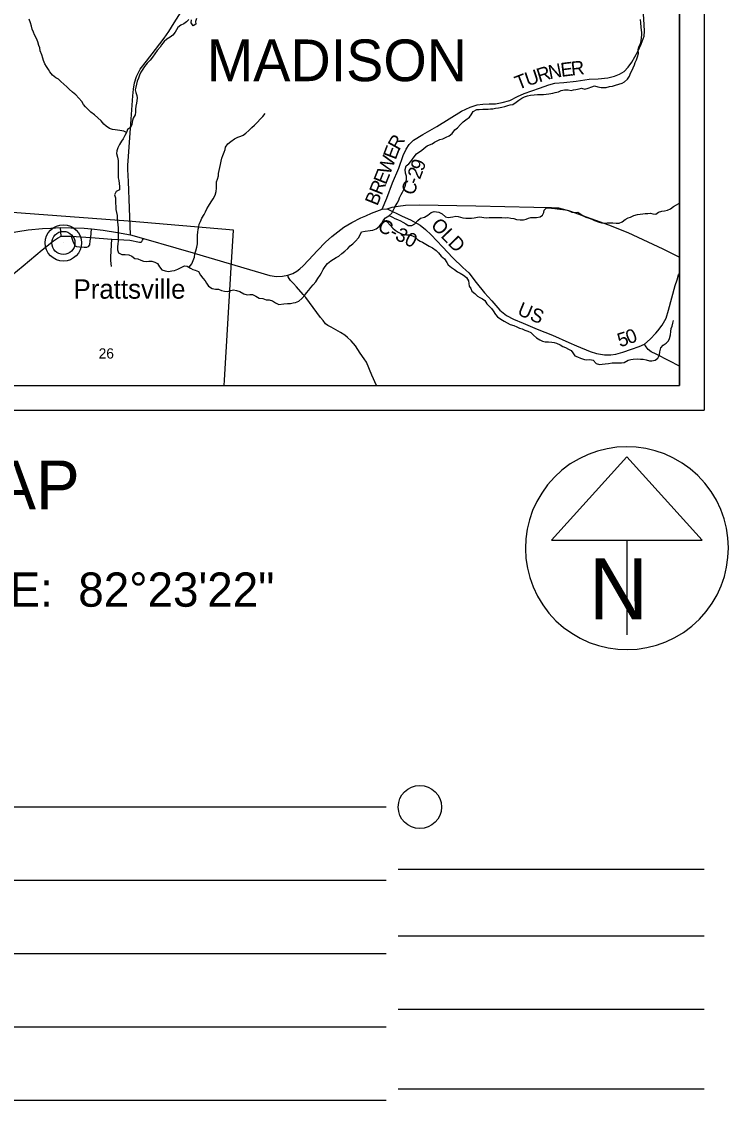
# Model space of a CAD drawing. Extents: x 0 to 34, y 0 to 22.
# Drawn here: x 6.21 to 9.099, y 11.177 to 15.589 of the extents above; entities that cross this region are included whole.
import ezdxf

# ---------------------------------------------------------------- set-up
doc = ezdxf.new("R2010")
doc.units = 0
for name, color, linetype in [('Default', 7, 'Continuous'), ('GM_X_County_Road', 7, 'Continuous'), ('GM_X_County_Road_Text', 7, 'Continuous'), ('GM_X_Minor_River', 7, 'Continuous'), ('GM_X_Section_Text', 7, 'Continuous'), ('GM_X_State_Route', 7, 'Continuous'), ('GM_X_Township_Road', 7, 'Continuous'), ('GM_X_Township_Text', 7, 'Continuous'), ('GM_X_Unincorporated', 7, 'Continuous'), ('GM_X_Unincorporated_Location', 7, 'Continuous'), ('GM_X_Unincorporated_Text', 7, 'Continuous'), ('GM_X_US_Route', 7, 'Continuous'), ('SC_Scratch1', 7, 'Continuous'), ('SH_Data', 7, 'Continuous'), ('SH_Text', 7, 'Continuous')]:
    doc.layers.add(name, color=color, linetype=linetype)

msp = doc.modelspace()

# ---------------------------------------------------------------- linework, layer by layer
at = {"layer": 'Default'}
msp.add_lwpolyline([(6.0561, 14.1), (7.0384, 14.1), (7.0398, 14.1229), (7.0661, 14.5598), (7.0761, 14.7365), (6.6458, 14.7734), (6.1161, 14.8127)], close=True, dxfattribs=at)
at = {"layer": 'GM_X_County_Road'}
for points in [[(7.6842, 14.8215), (7.7027, 14.8671), (7.7267, 14.9301), (7.7517, 14.9896), (7.7701, 15.0412), (7.7821, 15.0675), (7.7941, 15.0865), (7.8128, 15.1036), (7.8505, 15.1277), (7.9072, 15.1601), (8.0084, 15.2229), (8.0433, 15.2391), (8.0724, 15.2486), (8.0952, 15.2514), (8.1215, 15.2524), (8.1477, 15.253), (8.174, 15.2574), (8.206, 15.2663), (8.2379, 15.2831), (8.2642, 15.2954), (8.3269, 15.3173), (8.3652, 15.3299), (8.3893, 15.3372), (8.4272, 15.3404), (8.4773, 15.3454), (8.5301, 15.3534), (8.5672, 15.3549), (8.6061, 15.3584), (8.6336, 15.3654), (8.6545, 15.3733), (8.6729, 15.385), (8.6897, 15.4027), (8.7052, 15.4227), (8.7289, 15.4664), (8.7422, 15.4964), (8.7549, 15.529), (8.7568, 15.5503), (8.7555, 15.5753), (8.7526, 15.6202)], [(7.7042, 14.8235), (7.7656, 14.7937), (7.8006, 14.7775), (7.8391, 14.7557), (7.8619, 14.7386), (7.8844, 14.7165), (7.9302, 14.6678), (7.9733, 14.6221), (8.0133, 14.583), (8.0379, 14.5614), (8.068, 14.5218), (8.1018, 14.4791), (8.1322, 14.4467), (8.1645, 14.4085), (8.1917, 14.3863), (8.2212, 14.3717), (8.2604, 14.3559), (8.3171, 14.3312), (8.3807, 14.3058), (8.4472, 14.2768), (8.4788, 14.2632), (8.5339, 14.2401), (8.5599, 14.2309), (8.5928, 14.2264), (8.6184, 14.2264), (8.639, 14.229), (8.6678, 14.2363), (8.7033, 14.2486), (8.7343, 14.2603), (8.7564, 14.27)], [(6.147, 14.5332), (6.2168, 14.5903), (6.2945, 14.6549), (6.3413, 14.6925), (6.3566, 14.7035), (6.3721, 14.7117), (6.4137, 14.7116), (6.4931, 14.7064), (6.5788, 14.6994), (6.6531, 14.6952), (6.6926, 14.6869), (6.6988, 14.6871), (6.7013, 14.6898), (6.7047, 14.6951), (6.7093, 14.7021)], [(8.7564, 14.27), (8.7792, 14.2907), (8.8023, 14.3144), (8.8109, 14.3239), (8.8289, 14.3471), (8.8445, 14.3765), (8.8543, 14.4081), (8.8685, 14.4597), (8.8824, 14.5098), (8.8894, 14.5329), (8.8951, 14.5537), (8.9, 14.5591)], [(8.9, 14.1792), (8.8566, 14.2017), (8.8037, 14.2284), (8.7835, 14.238), (8.7717, 14.2484), (8.7633, 14.2588), (8.7564, 14.27)]]:
    msp.add_lwpolyline(points, dxfattribs=at)
at = {"layer": 'GM_X_Minor_River'}
for points in [[(6.286, 15.4699), (6.2845, 15.4822), (6.281, 15.4917), (6.2765, 15.5057), (6.2719, 15.5194), (6.2635, 15.5345), (6.2593, 15.5451), (6.2543, 15.558), (6.2509, 15.5705), (6.247, 15.5838), (6.2417, 15.5985)], [(6.8939, 15.5979), (6.8849, 15.5884), (6.8739, 15.58), (6.8615, 15.5739), (6.8497, 15.5648), (6.843, 15.5549), (6.8388, 15.5454), (6.8283, 15.5332), (6.8177, 15.5256), (6.8045, 15.5165), (6.7932, 15.507), (6.7818, 15.4945), (6.7766, 15.485), (6.7641, 15.4702)], [(6.925, 15.6021), (6.9212, 15.5888), (6.922, 15.5778), (6.9122, 15.571), (6.9034, 15.5835), (6.9053, 15.5964)], [(8.7308, 15.4736), (8.7338, 15.4855), (8.7395, 15.498), (8.7421, 15.5105), (8.744, 15.5223), (8.7455, 15.5348), (8.7455, 15.5447), (8.7447, 15.5545), (8.7432, 15.5655), (8.7409, 15.5845), (8.7405, 15.5978)], [(6.6394, 15.1354), (6.6278, 15.1408), (6.6123, 15.1439), (6.6025, 15.145), (6.5926, 15.1458), (6.5824, 15.1474), (6.5692, 15.1523), (6.556, 15.1607), (6.5461, 15.1701), (6.5352, 15.1827), (6.5216, 15.1956), (6.5088, 15.2073), (6.4937, 15.2191), (6.4827, 15.2294), (6.4718, 15.24), (6.4631, 15.2502), (6.4567, 15.2627), (6.4442, 15.2764), (6.4321, 15.2893), (6.4185, 15.2999), (6.4049, 15.3128), (6.3951, 15.3223), (6.383, 15.3326), (6.371, 15.3444), (6.3611, 15.3531), (6.3498, 15.3588), (6.3373, 15.3702), (6.3264, 15.3831), (6.3211, 15.3933), (6.3124, 15.4058), (6.306, 15.4161), (6.2996, 15.4293), (6.297, 15.4388), (6.2928, 15.4529), (6.286, 15.4699)], [(6.7641, 15.4702), (6.755, 15.4567), (6.7455, 15.4435), (6.7353, 15.4306), (6.7243, 15.4192), (6.7122, 15.4052), (6.7065, 15.395), (6.6974, 15.3818), (6.6925, 15.3696), (6.6883, 15.3579), (6.6833, 15.3458), (6.6807, 15.3337), (6.6776, 15.3212), (6.6746, 15.3094), (6.6776, 15.2996), (6.6821, 15.287), (6.6832, 15.2772), (6.6821, 15.2643), (6.6798, 15.2548), (6.6771, 15.2431), (6.6756, 15.2302), (6.6763, 15.2181), (6.6748, 15.2082), (6.6661, 15.1935), (6.6619, 15.1791), (6.6615, 15.1666), (6.6554, 15.156), (6.6437, 15.1473), (6.6391, 15.1348), (6.6323, 15.1226), (6.6259, 15.1101), (6.619, 15.1003), (6.6111, 15.0863), (6.6039, 15.073), (6.5997, 15.0605), (6.5985, 15.0488), (6.6023, 15.0351), (6.6049, 15.0215), (6.6056, 15.0086), (6.6056, 14.9991), (6.6048, 14.987), (6.6048, 14.9643), (6.6055, 14.9506), (6.6082, 14.9385), (6.6093, 14.9264), (6.6108, 14.9142), (6.6108, 14.9014), (6.5968, 14.8946), (6.5907, 14.8809), (6.5944, 14.8688), (6.594, 14.8552), (6.5948, 14.8445), (6.5959, 14.8339), (6.5963, 14.8203), (6.5989, 14.8078), (6.6004, 14.7956), (6.6011, 14.7828), (6.6018, 14.7695), (6.6033, 14.7574), (6.6052, 14.7449), (6.6056, 14.7316), (6.6052, 14.7179), (6.6055, 14.7058), (6.6051, 14.6922), (6.6036, 14.6793), (6.6028, 14.6691), (6.6028, 14.6558), (6.6069, 14.6433), (6.6198, 14.6361), (6.6342, 14.6364), (6.6485, 14.6353), (6.661, 14.6299), (6.6727, 14.6197), (6.6852, 14.6182), (6.698, 14.6128), (6.7082, 14.6087), (6.7207, 14.6075), (6.7305, 14.6094), (6.743, 14.6094), (6.7551, 14.6052), (6.7665, 14.5991), (6.7744, 14.5866), (6.7834, 14.5733), (6.7978, 14.5702), (6.8114, 14.5672), (6.8243, 14.5691), (6.8349, 14.5713), (6.8489, 14.5758), (6.8621, 14.5838), (6.8761, 14.5898), (6.8878, 14.5887), (6.9003, 14.5807), (6.9105, 14.5754), (6.9203, 14.572), (6.9332, 14.5662), (6.9411, 14.5518), (6.9517, 14.5393), (6.9604, 14.5291), (6.966, 14.5196), (6.9743, 14.5067), (6.9887, 14.4976)], [(8.2555, 15.2757), (8.2654, 15.2818), (8.2783, 15.2856), (8.2904, 15.2875), (8.3059, 15.289), (8.3192, 15.2902), (8.3332, 15.2906), (8.3442, 15.291), (8.3548, 15.2921), (8.365, 15.2933), (8.3813, 15.2967), (8.3915, 15.299), (8.4051, 15.3017), (8.4157, 15.3066), (8.4294, 15.31), (8.4441, 15.3093), (8.4566, 15.3074), (8.4665, 15.3105), (8.4763, 15.3109), (8.4888, 15.3139), (8.4987, 15.3166), (8.5131, 15.3128), (8.5263, 15.3166), (8.5411, 15.3227), (8.5517, 15.3258), (8.5653, 15.3224), (8.5786, 15.3197), (8.5892, 15.3194), (8.5994, 15.3198), (8.6127, 15.324), (8.6256, 15.3255), (8.6384, 15.3285), (8.6517, 15.3335), (8.6646, 15.3365), (8.6752, 15.3426), (8.6869, 15.3529), (8.6945, 15.3662), (8.6997, 15.3779), (8.7043, 15.3874), (8.7103, 15.4003), (8.7152, 15.4121), (8.7186, 15.4216), (8.7232, 15.4329), (8.7284, 15.4455), (8.7315, 15.4587), (8.7308, 15.4736)], [(7.2616, 14.4317), (7.2823, 14.4347), (7.2971, 14.4363), (7.31, 14.4366), (7.3198, 14.4382), (7.33, 14.4401), (7.3433, 14.4462), (7.3562, 14.4568), (7.3675, 14.4697), (7.3747, 14.4792), (7.3845, 14.4906), (7.3928, 14.5012), (7.4019, 14.5122), (7.4125, 14.5248), (7.4216, 14.5384), (7.4303, 14.5513), (7.436, 14.5612), (7.4435, 14.5745), (7.4511, 14.5874), (7.4613, 14.5995), (7.4738, 14.6106), (7.4855, 14.6178), (7.4961, 14.6239), (7.5071, 14.6299), (7.5199, 14.6398), (7.5321, 14.6497), (7.5442, 14.6611), (7.5536, 14.6713), (7.5638, 14.6801), (7.5756, 14.6911), (7.5873, 14.704), (7.5941, 14.7165), (7.5998, 14.7294), (7.6149, 14.7325), (7.6354, 14.734), (7.646, 14.7356), (7.66, 14.7409), (7.6725, 14.7512), (7.6827, 14.7648), (7.6895, 14.7766), (7.6982, 14.7868), (7.7114, 14.7944), (7.7232, 14.8058), (7.7311, 14.8187), (7.7379, 14.8328), (7.7458, 14.8457), (7.7519, 14.8582), (7.7557, 14.8681), (7.7617, 14.8813), (7.7674, 14.8916), (7.7738, 14.9056), (7.7798, 14.9193), (7.7828, 14.9341), (7.784, 14.9458), (7.7832, 14.9565), (7.779, 14.9697), (7.7786, 14.9841), (7.782, 14.9986), (7.7926, 15.0069), (7.8009, 15.0164), (7.8085, 15.0259), (7.8149, 15.0365), (7.824, 15.0479), (7.8346, 15.0544), (7.8456, 15.062), (7.8562, 15.0719), (7.8683, 15.0802), (7.8781, 15.0848), (7.8883, 15.089), (7.8982, 15.0958), (7.9084, 15.1019), (7.9201, 15.1065), (7.9315, 15.1099), (7.9459, 15.1163), (7.9584, 15.1224), (7.9697, 15.1315), (7.9811, 15.1456), (7.9924, 15.1551), (8.0045, 15.168), (8.0159, 15.1794), (8.0265, 15.1874), (8.0405, 15.1976), (8.0473, 15.2071), (8.0564, 15.2208), (8.0707, 15.2288), (8.0806, 15.2299), (8.095, 15.2307), (8.1067, 15.2303), (8.1173, 15.2304), (8.1272, 15.2319), (8.137, 15.2327), (8.1476, 15.2342), (8.1598, 15.2361), (8.173, 15.2384), (8.1859, 15.2418), (8.198, 15.2456), (8.2078, 15.2483), (8.2181, 15.2502), (8.2321, 15.2597), (8.2423, 15.2673), (8.2555, 15.2757)], [(6.8951, 14.584), (6.9064, 14.5977), (6.9117, 14.6114), (6.9174, 14.6261), (6.9189, 14.6394), (6.9227, 14.6519), (6.9265, 14.6663), (6.9288, 14.6796), (6.9289, 14.6906), (6.9296, 14.7034), (6.93, 14.7167), (6.9304, 14.7269), (6.932, 14.7402), (6.9342, 14.7497), (6.9369, 14.7599), (6.9415, 14.772), (6.9475, 14.7853), (6.9566, 14.8), (6.9623, 14.811), (6.968, 14.8235), (6.9741, 14.8345), (6.9851, 14.8512), (6.9931, 14.864), (7.001, 14.8788), (7.0056, 14.8943), (7.0075, 14.9072), (7.0075, 14.933), (7.0106, 14.9443), (7.0148, 14.958), (7.0159, 14.9682), (7.0182, 14.9803), (7.0209, 14.9921), (7.0228, 15.0038), (7.0262, 15.0178), (7.0285, 15.03), (7.0331, 15.0413), (7.0388, 15.055), (7.0426, 15.0652), (7.0445, 15.0747), (7.0532, 15.089), (7.0657, 15.0989), (7.0808, 15.1098), (7.0937, 15.1159), (7.1066, 15.1197), (7.1164, 15.1238), (7.1274, 15.1333), (7.1387, 15.1431), (7.1512, 15.1552), (7.1626, 15.1651), (7.1751, 15.1779), (7.185, 15.1897), (7.1963, 15.2002), (7.2066, 15.2135)], [(7.7124, 14.7954), (7.7266, 14.7884), (7.7361, 14.7839), (7.7463, 14.7793), (7.7588, 14.7744), (7.7687, 14.7683), (7.7812, 14.7623), (7.791, 14.7555), (7.805, 14.7547), (7.8183, 14.7623), (7.83, 14.7756), (7.841, 14.7848), (7.8569, 14.7886), (7.8709, 14.7969), (7.8838, 14.8083), (7.897, 14.8129), (7.9065, 14.8106), (7.9163, 14.8099), (7.9292, 14.8027), (7.9433, 14.791), (7.9535, 14.7879), (7.9633, 14.7891), (7.9736, 14.7902), (7.9853, 14.7925), (7.9951, 14.7922), (8.0046, 14.7895), (8.0145, 14.7861), (8.0258, 14.785), (8.0368, 14.785), (8.0489, 14.7854), (8.0603, 14.787), (8.0732, 14.7885), (8.083, 14.79), (8.0993, 14.7881), (8.1107, 14.787), (8.1209, 14.7874), (8.1308, 14.7874), (8.1421, 14.7878), (8.1531, 14.7882), (8.1626, 14.7882), (8.1736, 14.7871), (8.1868, 14.7864), (8.1982, 14.7871), (8.2103, 14.7856), (8.2217, 14.783), (8.2338, 14.78), (8.2482, 14.7777), (8.2615, 14.7778), (8.2721, 14.7808), (8.2819, 14.785), (8.2921, 14.7873), (8.3024, 14.7873), (8.3149, 14.7881), (8.3296, 14.7911), (8.3398, 14.7976), (8.3448, 14.8078), (8.3463, 14.8181), (8.3561, 14.8272), (8.3656, 14.8272), (8.3762, 14.8261), (8.3894, 14.8242), (8.3989, 14.8235), (8.4103, 14.8223), (8.4228, 14.8208), (8.4338, 14.8193), (8.4463, 14.8163), (8.4588, 14.8095), (8.4713, 14.8088), (8.4845, 14.8092), (8.4955, 14.802), (8.5054, 14.7944), (8.5164, 14.7887), (8.53, 14.785), (8.541, 14.7808), (8.5524, 14.7755), (8.5668, 14.7695), (8.5804, 14.7653), (8.5899, 14.7646), (8.6035, 14.7665), (8.6172, 14.7665), (8.6266, 14.7657), (8.6403, 14.7639), (8.6535, 14.7646), (8.6645, 14.77), (8.6774, 14.7802), (8.6891, 14.7867), (8.699, 14.789), (8.7122, 14.7954), (8.7274, 14.8004), (8.7387, 14.8012), (8.7489, 14.8023), (8.7595, 14.8046), (8.7705, 14.8042), (8.7808, 14.8058), (8.791, 14.8028), (8.8031, 14.802), (8.8133, 14.8092), (8.8277, 14.8134), (8.8383, 14.815), (8.8504, 14.8173), (8.8622, 14.823)], [(8.8622, 14.823), (8.8754, 14.8332), (8.8868, 14.8397), (8.8966, 14.845), (8.9, 14.8473)], [(7.6898, 14.777), (7.7043, 14.7705), (7.7164, 14.7561), (7.7274, 14.744), (7.7369, 14.7361), (7.749, 14.7281), (7.7634, 14.7213), (7.7729, 14.7179), (7.7831, 14.7168), (7.7949, 14.7164), (7.8081, 14.7134), (7.8184, 14.707), (7.8282, 14.6979), (7.8392, 14.6903), (7.8487, 14.6862), (7.8631, 14.6786), (7.876, 14.6703), (7.8896, 14.6642), (7.9044, 14.6521), (7.9143, 14.6434), (7.9256, 14.6301), (7.9385, 14.6184), (7.9484, 14.6036), (7.9541, 14.5938), (7.9674, 14.5832), (7.9803, 14.5749), (7.9916, 14.5658), (8.0034, 14.5605), (8.0163, 14.5525), (8.0284, 14.5419), (8.0368, 14.529), (8.0387, 14.5177), (8.0398, 14.5063), (8.0463, 14.4968), (8.0512, 14.4862), (8.0633, 14.4768), (8.0732, 14.4658), (8.0827, 14.4612), (8.0937, 14.4556), (8.1032, 14.4476), (8.1126, 14.4347), (8.121, 14.4249), (8.1305, 14.4154), (8.1373, 14.4056), (8.1468, 14.3915), (8.1559, 14.3813), (8.1688, 14.3715), (8.1824, 14.3635), (8.1957, 14.3571), (8.2078, 14.3503), (8.2226, 14.3454), (8.2351, 14.3405), (8.2457, 14.3356), (8.256, 14.3318), (8.2677, 14.3272), (8.2802, 14.3223), (8.2923, 14.3174), (8.3033, 14.3061), (8.3147, 14.2954), (8.328, 14.2871), (8.3401, 14.2826), (8.3503, 14.2796), (8.3636, 14.2796), (8.3772, 14.2777), (8.3867, 14.2758), (8.3966, 14.2736), (8.4113, 14.2668), (8.4231, 14.2607), (8.4337, 14.2554), (8.4455, 14.249), (8.4572, 14.2437), (8.464, 14.2338), (8.472, 14.2225), (8.4819, 14.2183), (8.4947, 14.2119), (8.5114, 14.2066), (8.5209, 14.2055), (8.5334, 14.2063), (8.5463, 14.2036), (8.5584, 14.1907), (8.572, 14.1862), (8.583, 14.1881), (8.5952, 14.1893), (8.6088, 14.1901), (8.6243, 14.1927), (8.6345, 14.1931), (8.6512, 14.1935), (8.6622, 14.1935), (8.6739, 14.1951), (8.6898, 14.2038), (8.7004, 14.2069), (8.7103, 14.208), (8.7277, 14.2092), (8.7394, 14.2084), (8.7504, 14.2081), (8.7637, 14.2058), (8.777, 14.2013), (8.7864, 14.2013), (8.7993, 14.2043), (8.8114, 14.212), (8.8182, 14.2264)], [(6.9887, 14.4976), (7.0023, 14.4941), (7.0148, 14.4941), (7.0276, 14.4896), (7.0401, 14.4861), (7.0533, 14.4857), (7.0662, 14.4895), (7.0772, 14.4918), (7.0889, 14.4895), (7.1029, 14.4849), (7.1184, 14.475), (7.1323, 14.4708), (7.1433, 14.4727), (7.1543, 14.4727), (7.1675, 14.4658), (7.1819, 14.4579), (7.1962, 14.4571), (7.2098, 14.451), (7.2223, 14.4506), (7.2359, 14.4468), (7.248, 14.4388), (7.2616, 14.4317)], [(8.8182, 14.2264), (8.8193, 14.2385), (8.8231, 14.2548), (8.8329, 14.2658), (8.8443, 14.2738), (8.8541, 14.2833), (8.8587, 14.2928), (8.8624, 14.3083), (8.8639, 14.3216), (8.8654, 14.3334), (8.8688, 14.3429), (8.8726, 14.3558), (8.8749, 14.366)]]:
    msp.add_lwpolyline(points, dxfattribs=at)
at = {"layer": 'GM_X_State_Route'}
msp.add_lwpolyline([(6.6553, 14.7165), (6.6473, 14.935), (6.6452, 14.9843), (6.6452, 15.0012), (6.6457, 15.0194), (6.6551, 15.1513), (6.6652, 15.2853), (6.6678, 15.3121), (6.6722, 15.3387), (6.6801, 15.3647), (6.6954, 15.3942), (6.7209, 15.4273), (6.7573, 15.4749), (6.7925, 15.5206), (6.812, 15.5481), (6.8346, 15.5838), (6.933, 15.7423)], dxfattribs=at)
at = {"layer": 'GM_X_Township_Road'}
for p, q in [((6.3721, 14.7117), (6.3698, 14.7463)), ((6.4931, 14.7064), (6.4957, 14.7412))]:
    msp.add_line(p, q, dxfattribs=at)
for points in [[(6.4137, 14.7116), (6.4214, 14.6871), (6.4292, 14.6725), (6.4352, 14.6689), (6.4469, 14.6676), (6.4667, 14.667), (6.4776, 14.6665), (6.4844, 14.6686), (6.4888, 14.6756), (6.4909, 14.6923), (6.4931, 14.7064)], [(6.5775, 14.5872), (6.5752, 14.6114), (6.5747, 14.6275), (6.5788, 14.6994)], [(7.6607, 14.1), (7.6425, 14.1432), (7.6204, 14.1961), (7.6102, 14.21), (7.5938, 14.2325), (7.5748, 14.2625), (7.557, 14.2834), (7.5431, 14.2967), (7.5311, 14.3062), (7.5134, 14.3176), (7.476, 14.3398), (7.4621, 14.3461), (7.4532, 14.3527), (7.4434, 14.366), (7.4317, 14.379), (7.3725, 14.4601), (7.3611, 14.473), (7.3336, 14.5041), (7.3212, 14.5183), (7.3095, 14.5307), (7.3041, 14.5376), (7.3003, 14.5455), (7.2987, 14.5522)]]:
    msp.add_lwpolyline(points, dxfattribs=at)
at = {"layer": 'GM_X_Unincorporated'}
for radius in [0.0744, 0.0472]:
    msp.add_circle((6.3814, 14.6838), radius, dxfattribs=at)
at = {"layer": 'GM_X_Unincorporated_Location'}
msp.add_line((6.3814, 14.6838), (6.3814, 14.6838), dxfattribs=at)
at = {"layer": 'GM_X_US_Route'}
for points in [[(6.9119, 14.6429), (6.9158, 14.6418), (7.2257, 14.551), (7.252, 14.5464), (7.2762, 14.5471), (7.2987, 14.5522), (7.3187, 14.5591), (7.3351, 14.568), (7.3481, 14.5775), (7.3617, 14.5902), (7.383, 14.6133), (7.42, 14.6525), (7.453, 14.6863), (7.4779, 14.7098), (7.5273, 14.7478), (7.5599, 14.7674), (7.5969, 14.7867), (7.6175, 14.795), (7.6412, 14.8051), (7.6842, 14.8215), (7.7042, 14.8235), (7.7248, 14.8295), (7.7495, 14.8336), (7.7799, 14.838), (7.8359, 14.8402), (8.0664, 14.8352), (8.3047, 14.8304), (8.3766, 14.8288), (8.3883, 14.8279), (8.4048, 14.8269), (8.45, 14.8152), (8.6086, 14.7576), (8.6884, 14.7268), (8.8312, 14.6589), (8.9, 14.626)], [(5.5748, 14.6035), (5.7069, 14.6307), (5.752, 14.6403), (5.9774, 14.6861), (6.094, 14.7105), (6.1574, 14.7235), (6.1954, 14.7305), (6.2378, 14.7366), (6.2962, 14.7427), (6.3296, 14.7447), (6.3698, 14.7463), (6.4115, 14.746), (6.4229, 14.746), (6.4667, 14.744), (6.4957, 14.7412), (6.5432, 14.736), (6.6028, 14.7269), (6.6553, 14.7165)], [(6.6553, 14.7165), (6.7093, 14.7021), (6.841, 14.6636), (6.9119, 14.6429)]]:
    msp.add_lwpolyline(points, dxfattribs=at)
at = {"layer": 'SC_Scratch1'}
msp.add_lwpolyline([(5.0535, 14.1), (8.9, 14.1), (8.9, 18.7389), (8.2061, 18.7863), (7.2159, 18.8539), (6.8273, 18.8804), (5.9889, 18.9377), (5.4885, 18.9719), (5.4007, 18.9779), (5.3662, 18.4999), (5.3506, 18.2846), (5.2869, 17.4026), (5.2761, 17.2534), (5.1794, 15.9156), (5.1049, 14.8414), (5.0814, 14.5016)], close=True, dxfattribs=at)
at = {"layer": 'SH_Data'}
for p, q in [((9, 21), (9, 14)), ((8.9, 20.9), (8.9, 14.1)), ((2.1, 14.1), (8.9, 14.1)), ((2, 14), (9, 14)), ((8.6845, 13.8091), (8.3769, 13.4678)), ((8.9921, 13.4678), (8.6845, 13.8091)), ((8.3769, 13.4678), (8.9921, 13.4678)), ((8.6845, 13.4678), (8.6845, 13.0811)), ((8.6845, 13.4353), (8.6845, 13.4353)), ((8.6845, 13.4353), (8.6845, 13.4353)), ((7.7, 12.3767), (4.4937, 12.3767)), ((9, 12.1207), (7.75, 12.1207)), ((7.7, 12.0767), (3.9895, 12.0767)), ((9, 11.8491), (7.75, 11.8491)), ((7.7, 11.7767), (3.6192, 11.7767)), ((9, 11.5491), (7.75, 11.5491)), ((7.7, 11.4767), (3.3288, 11.4767)), ((9, 11.2223), (7.75, 11.2223)), ((7.7, 11.1767), (4.7452, 11.1767))]:
    msp.add_line(p, q, dxfattribs=at)
msp.add_arc((8.6845, 13.4353), 0.4148, 129.7798, 129.7633, dxfattribs=at)
at = {"layer": 'SH_Text'}
msp.add_circle((7.8383, 12.3767), 0.0883, dxfattribs=at)

# ---------------------------------------------------------------- texts
at = {"layer": 'GM_X_County_Road_Text'}
for s, height, rotation, p in [('R', 0.0568, 17.3019, (8.3258, 15.3398)), ('N', 0.0568, 11.2221, (8.3688, 15.3533)), ('E', 0.0568, 6.9124, (8.4167, 15.3628)), ('R', 0.0568, 6.5402, (8.4588, 15.3679)), ('T', 0.0568, 21.1178, (8.2397, 15.3089)), ('U', 0.0568, 18.5041, (8.2787, 15.324)), ('R', 0.0568, 60.7092, (7.7533, 15.0587)), ('W', 0.0568, 68.9712, (7.7154, 14.9593)), ('E', 0.0568, 69.1729, (7.7391, 15.021)), ('9', 0.0568, 69.9774, (7.851, 14.9742)), ('E', 0.0568, 68.1071, (7.6993, 14.9191)), ('2', 0.0568, 69.1721, (7.8383, 14.9407)), ('R', 0.0568, 68.1026, (7.6818, 14.8758)), ('C', 0.0568, 68.0217, (7.8117, 14.8746)), ('-', 0.0568, 68.2213, (7.8293, 14.9181)), ('B', 0.0568, 68.0986, (7.6644, 14.8324)), ('C-30', 0.05682, 333.4407, (7.6616, 14.7355)), ('OLD', 0.05682, 313.8399, (7.8798, 14.7528)), ('US', 0.05682, 337.3781, (8.233, 14.3914)), ('5', 0.0568, 17.7619, (8.6561, 14.2566)), ('0', 0.0568, 20.6192, (8.6924, 14.2683))]:
    msp.add_text(s, height=height, rotation=rotation, dxfattribs=at).set_placement(p)
at = {"layer": 'GM_X_Section_Text'}
msp.add_text('26', height=0.04186, rotation=0, dxfattribs=at).set_placement((6.5256, 14.2108))
at = {"layer": 'GM_X_Township_Text'}
msp.add_text('MADISON', height=0.17045, rotation=0, dxfattribs=at).set_placement((6.9673, 15.3453))
at = {"layer": 'GM_X_Unincorporated_Text'}
msp.add_text('Prattsville', height=0.078977, rotation=0, dxfattribs=at).set_placement((6.4227, 14.4557))
at = {"layer": 'SH_Data'}
msp.add_text('N', height=0.25, dxfattribs=at).set_placement((8.5292, 13.144))
at = {"layer": 'SH_Text'}
for s, height, p in [('LOCATION MAP', 0.2, (4.4269, 13.5938)), ('LATITUDE:  39°16\'29"     LONGITUDE:  82°23\'22"', 0.14, (3.071, 13.1959))]:
    msp.add_text(s, height=height, dxfattribs=at).set_placement(p)

doc.saveas('drawing.dxf')
